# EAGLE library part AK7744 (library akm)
ADC + Audio DSP 24-Bit, 3 ch ADC /4ch DAC and Input Selector
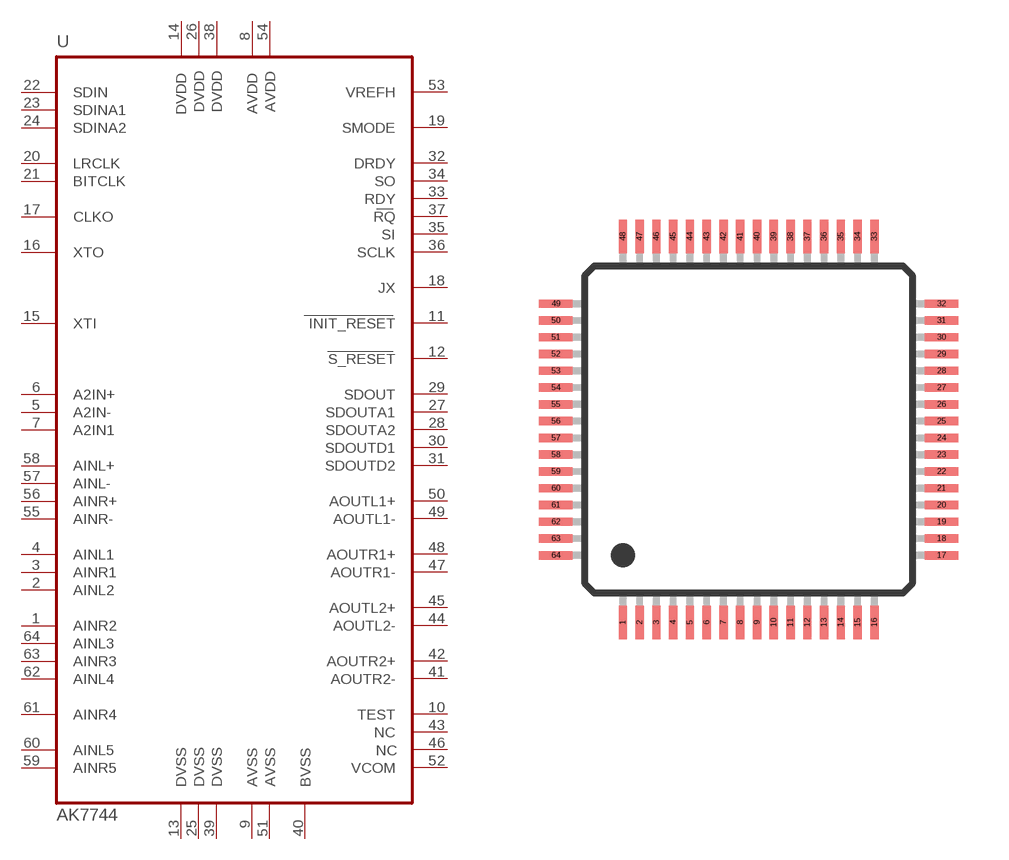
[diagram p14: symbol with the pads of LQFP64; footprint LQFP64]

Designator prefix U

## AK7744  [LQFP64]
1  AINR2  in
2  AINL2  in
3  AINR1  in
4  AINL1  in
5  A2IN-  in
6  A2IN+  in
7  A2IN1  in
8  AVDD  pwr
9  AVSS  pwr
10  TEST
11  INIT_RESET  in
12  S_RESET  in
13  DVSS  pwr
14  DVDD  pwr
15  XTI  in
16  XTO  out
17  CLKO  out
18  JX  in
19  SMODE
20  LRCLK  out
21  BITCLK
22  SDIN  in
23  SDINA1  in
24  SDINA2  in
25  DVSS1  pwr
26  DVDD1  pwr
27  SDOUTA1  out
28  SDOUTA2  out
29  SDOUT  out
30  SDOUTD1  out
31  SDOUTD2  out
32  DRDY  out
33  RDY  out
34  SO
35  SI  in
36  SCLK  in
37  RQ  in
38  DVDD2  pwr
39  DVSS2  pwr
40  BVSS  pwr
41  AOUTR2-  out
42  AOUTR2+  out
43  NC
44  AOUTL2-  out
45  AOUTL2+  out
46  NC1
47  AOUTR1-  out
48  AOUTR1+  out
49  AOUTL1-  out
50  AOUTL1+  out
51  AVSS1  pwr
52  VCOM  out
53  VREFH  in
54  AVDD2  pwr
55  AINR-  in
56  AINR+  in
57  AINL-  in
58  AINL+  in
59  AINR5  in
60  AINL5  in
61  AINR4  in
62  AINL4  in
63  AINR3  in
64  AINL3  in

## Footprint LQFP64 (pad centres in mm)
LQFP64
smd 0.25 x 1: 1 -3.75,-5.75; 2 -3.25,-5.75; 3 -2.75,-5.75; 4 -2.25,-5.75; 5 -1.75,-5.75; 6 -1.25,-5.75; 7 -0.75,-5.75; 8 -0.25,-5.75; 9 0.25,-5.75; 10 0.75,-5.75; 11 1.25,-5.75; 12 1.75,-5.75; 13 2.25,-5.75; 14 2.75,-5.75; 15 3.25,-5.75; 16 3.75,-5.75; 33 3.75,5.75; 34 3.25,5.75; 35 2.75,5.75; 36 2.25,5.75; 37 1.75,5.75; 38 1.25,5.75; 39 0.75,5.75; 40 0.25,5.75; 41 -0.25,5.75; 42 -0.75,5.75; 43 -1.25,5.75; 44 -1.75,5.75; 45 -2.25,5.75; 46 -2.75,5.75; 47 -3.25,5.75; 48 -3.75,5.75
smd 1 x 0.25: 17 5.75,-3.75; 18 5.75,-3.25; 19 5.75,-2.75; 20 5.75,-2.25; 21 5.75,-1.75; 22 5.75,-1.25; 23 5.75,-0.75; 24 5.75,-0.25; 25 5.75,0.25; 26 5.75,0.75; 27 5.75,1.25; 28 5.75,1.75; 29 5.75,2.25; 30 5.75,2.75; 31 5.75,3.25; 32 5.75,3.75; 49 -5.75,3.75; 50 -5.75,3.25; 51 -5.75,2.75; 52 -5.75,2.25; 53 -5.75,1.75; 54 -5.75,1.25; 55 -5.75,0.75; 56 -5.75,0.25; 57 -5.75,-0.25; 58 -5.75,-0.75; 59 -5.75,-1.25; 60 -5.75,-1.75; 61 -5.75,-2.25; 62 -5.75,-2.75; 63 -5.75,-3.25; 64 -5.75,-3.75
